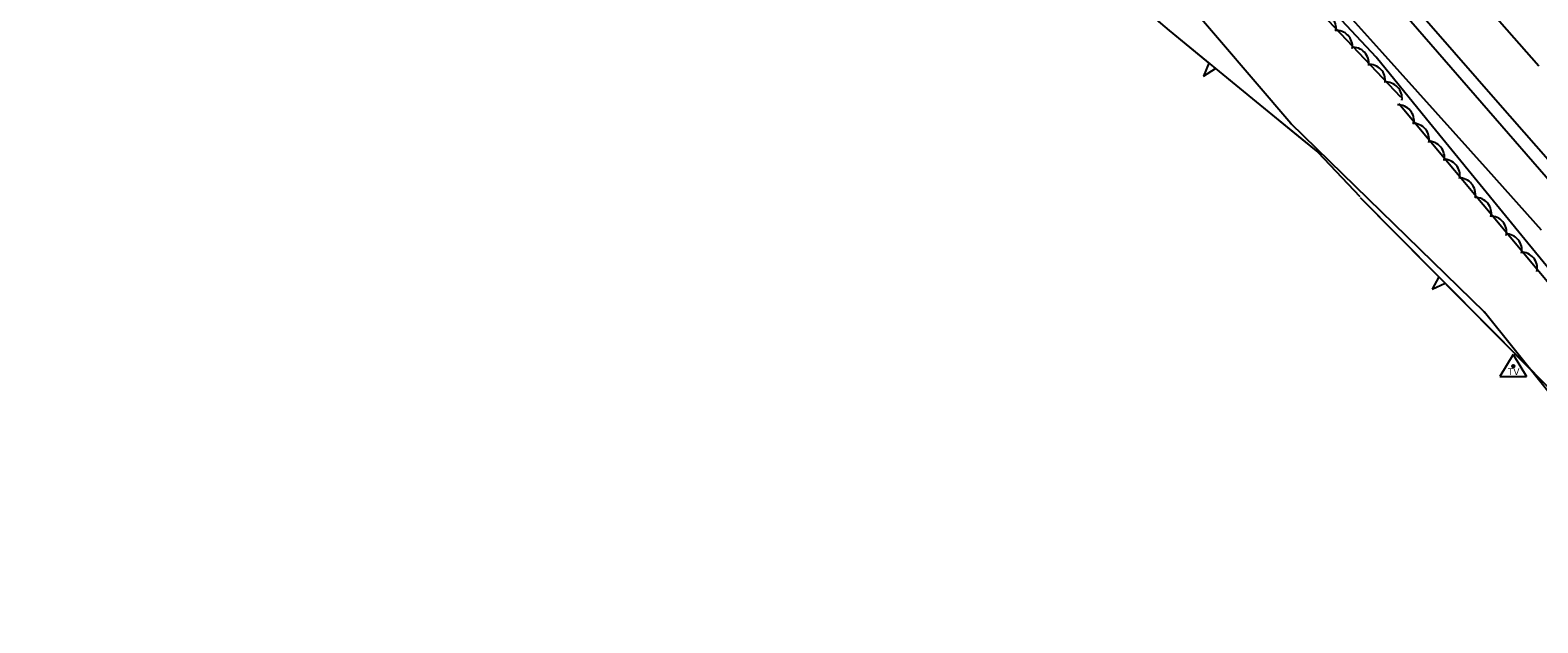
# Model space of a CAD drawing. Extents: x 954793 to 988390, y 1867850 to 1924428.
# Drawn here: x 966210.2 to 966547.2, y 1897451.7 to 1897584.2 of the extents above; entities that cross this region are included whole.
import ezdxf

# ---------------------------------------------------------------- set-up
doc = ezdxf.new("R2010")
doc.units = 0
for name, color, linetype in [('S_DITCHLINE', 7, 'Continuous'), ('S_EDGE_PAVEMENT', 7, 'Continuous'), ('S_FIBER_OPTIC_CABLE', 7, 'Continuous'), ('S_PAVEMENT_CROWN', 7, 'Continuous'), ('S_SECONDARY_CTL', 7, 'Continuous'), ('S_SHOULDER', 7, 'Continuous'), ('S_TREE', 7, 'Continuous'), ('S_UTL_PT_SYM', 7, 'Continuous')]:
    doc.layers.add(name, color=color, linetype=linetype)

msp = doc.modelspace()

# ---------------------------------------------------------------- linework, layer by layer
at = {"layer": 'S_DITCHLINE'}
for points in [[(966548.08, 1897539.52), (966536.22, 1897552.74), (966524.35, 1897565.95), (966512.49, 1897579.16), (966501.76, 1897591.19), (966491.03, 1897603.22), (966480.3, 1897615.25), (966469.57, 1897627.28), (966460.24, 1897637.75), (966450.92, 1897648.22), (966441.6, 1897658.68), (966432.28, 1897669.15), (966423.05, 1897680.35), (966413.83, 1897691.54), (966404.6, 1897702.74), (966395.38, 1897713.94), (966391.14, 1897724.13), (966393.13, 1897727.16)], [(966556.3, 1897522.78), (966544.99, 1897536.63), (966533.69, 1897550.47), (966522.38, 1897564.32), (966511.07, 1897578.17), (966500.09, 1897590.01)]]:
    msp.add_lwpolyline(points, dxfattribs=at)
at = {"layer": 'S_EDGE_PAVEMENT'}
msp.add_lwpolyline([(966552.72, 1897551.55), (966538.3, 1897568.05), (966523.89, 1897584.55), (966508.4, 1897602.27), (966492.92, 1897620), (966478.07, 1897636.95), (966463.21, 1897653.91), (966448.22, 1897671.09), (966433.23, 1897688.28), (966419.71, 1897703.72), (966406.18, 1897719.16), (966391.26, 1897736.29), (966376.34, 1897753.43), (966362.18, 1897769.63), (966348.01, 1897785.83), (966333.44, 1897802.55), (966318.86, 1897819.26), (966305.02, 1897834.99), (966291.18, 1897850.72)], dxfattribs=at)
at = {"layer": 'S_FIBER_OPTIC_CABLE'}
for p, q in [((966491.99, 1897563.37), (966422.2, 1897645.18)), ((966535.31, 1897521.19), (966491.99, 1897563.37)), ((966574.66, 1897471.98), (966535.31, 1897521.19))]:
    msp.add_line(p, q, dxfattribs=at)
at = {"layer": 'S_PAVEMENT_CROWN'}
msp.add_lwpolyline([(966547.45, 1897576.17), (966533.12, 1897592.54), (966517.5, 1897610.34), (966501.88, 1897628.13), (966487.04, 1897645.2), (966472.19, 1897662.27), (966457.21, 1897679.31), (966442.24, 1897696.35), (966428.96, 1897711.61), (966415.69, 1897726.86), (966400.57, 1897744.13), (966385.45, 1897761.4), (966371.47, 1897777.45), (966357.49, 1897793.5), (966342.57, 1897810.59), (966327.65, 1897827.67), (966313.88, 1897843.35)], dxfattribs=at)
at = {"layer": 'S_SECONDARY_CTL'}
for p, q in [((966541.75, 1897511.71), (966538.74, 1897506.76)), ((966541.75, 1897511.71), (966544.7, 1897506.76)), ((966538.74, 1897506.76), (966544.7, 1897506.76))]:
    msp.add_line(p, q, dxfattribs=at)
for radius in [0.311, 0.183, 0.103]:
    msp.add_circle((966541.75, 1897509.1), radius, dxfattribs=at)
at = {"layer": 'S_SHOULDER'}
msp.add_lwpolyline([(966550.56, 1897549.65), (966536.21, 1897566.22), (966521.85, 1897582.78), (966506.37, 1897600.54), (966490.9, 1897618.3), (966476.04, 1897635.16), (966461.19, 1897652.02), (966446.3, 1897669.33), (966431.41, 1897686.64), (966417.84, 1897702.11), (966404.28, 1897717.59), (966396.9, 1897725.99), (966391.86, 1897731.92), (966383.24, 1897741.9), (966374.62, 1897751.89), (966360.41, 1897768.12), (966346.2, 1897784.36), (966331.63, 1897800.98), (966317.06, 1897817.59), (966303.14, 1897833.34), (966289.22, 1897849.08)], dxfattribs=at)
at = {"layer": 'S_TREE'}
for p, q in [((966473.69, 1897576.89), (966472.51, 1897573.98)), ((966472.51, 1897573.98), (966475.21, 1897575.65)), ((966525.1, 1897529.07), (966523.63, 1897526.29)), ((966523.63, 1897526.29), (966526.48, 1897527.68))]:
    msp.add_line(p, q, dxfattribs=at)
for points in [[(966210.24, 1897890.13), (966252.56, 1897836.85), (966294.06, 1897795.15), (966307.68, 1897772.91), (966311.61, 1897754.04), (966330.07, 1897721.39), (966348.47, 1897687.31), (966364.51, 1897661.47), (966383.44, 1897643.98), (966402.93, 1897632.04), (966416.66, 1897623.5), (966438.97, 1897606.13), (966464.86, 1897584.15), (966484.3, 1897568.18), (966498.09, 1897556.96), (966507.44, 1897547.01)], [(966249.08, 1897872.34), (966354.07, 1897745.39), (966390.72, 1897702.43), (966457.35, 1897631.88), (966516.54, 1897569.35)], [(966454.51, 1897592.93), (966464.86, 1897584.15), (966473.69, 1897576.89)], [(966475.21, 1897575.65), (966484.3, 1897568.18), (966494.56, 1897559.82)], [(966516.16, 1897567.8), (966597.19, 1897470.7), (966605.89, 1897471.89), (966614.68, 1897465.94), (966625.32, 1897451.68)], [(966494.56, 1897559.82), (966498.09, 1897556.96), (966507.44, 1897547.01)], [(966507.5, 1897546.84), (966525.1, 1897529.07)], [(966507.5, 1897546.84), (966553.56, 1897500.33)], [(966526.48, 1897527.68), (966544.07, 1897509.91)], [(966544.07, 1897509.91), (966553.56, 1897500.33), (966561.24, 1897491.74)]]:
    msp.add_lwpolyline(points, dxfattribs=at)
for centre, start, end in [((966498.53, 1897584.5), 352.6325, 94.2294), ((966502.15, 1897580.58), 352.6325, 94.2294), ((966505.83, 1897576.79), 352.6325, 94.2294), ((966509.5, 1897572.97), 352.6325, 94.2294), ((966513.24, 1897569.01), 352.6325, 94.2294), ((966515.93, 1897563.92), 349.0451, 90.642), ((966519.29, 1897559.78), 349.0451, 90.642), ((966522.73, 1897555.77), 349.0451, 90.642), ((966526.16, 1897551.72), 349.0451, 90.642), ((966529.64, 1897547.54), 349.0451, 90.642), ((966533.23, 1897543.18), 349.0451, 90.642), ((966536.6, 1897539.04), 349.0451, 90.642), ((966540.04, 1897535.03), 349.0451, 90.642), ((966543.46, 1897530.98), 349.0451, 90.642)]:
    msp.add_arc(centre, 3.64, start, end, dxfattribs=at)
at = {"layer": 'S_UTL_PT_SYM'}
for points in [[(966491.99, 1897563.37), (966491.99, 1897563.42), (966491.99, 1897563.37), (966491.94, 1897563.37), (966491.99, 1897563.37), (966491.99, 1897563.32), (966491.99, 1897563.37), (966492.04, 1897563.37)], [(966535.31, 1897521.19), (966535.31, 1897521.24), (966535.31, 1897521.19), (966535.26, 1897521.19), (966535.31, 1897521.19), (966535.31, 1897521.14), (966535.31, 1897521.19), (966535.36, 1897521.19)]]:
    msp.add_lwpolyline(points, dxfattribs=at)

# ---------------------------------------------------------------- texts
at = {"layer": 'S_SECONDARY_CTL'}
msp.add_text('TV', height=1.5, rotation=360, dxfattribs=at).set_placement((966540.55, 1897507.09))

doc.saveas('drawing.dxf')
